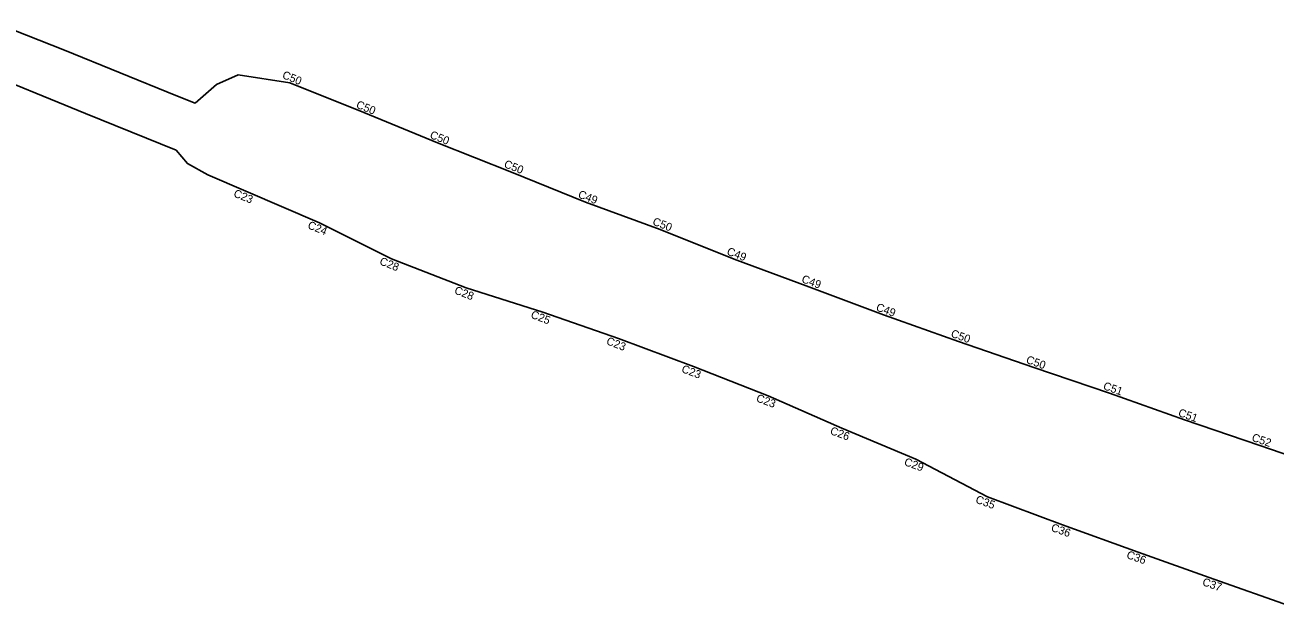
# Model space of a CAD drawing. Extents: x 2164037 to 2171931, y 206073 to 210167.
# Drawn here: x 2165609 to 2166391, y 209174 to 209537 of the extents above; entities that cross this region are included whole.
import ezdxf

# ---------------------------------------------------------------- set-up
doc = ezdxf.new("R2010")
doc.units = 0
doc.layers.add('RD_PD_CstnLmt', color=7, linetype='Continuous')
doc.layers.add('RD_PD_TX_CstnLmt', color=7, linetype='Continuous')

msp = doc.modelspace()

# ---------------------------------------------------------------- linework, layer by layer
at = {"layer": 'RD_PD_CstnLmt'}
for p, q in [((2165774.87, 209500.63), (2165821.08, 209482.09)), ((2165821.08, 209482.09), (2165867.16, 209463.21)), ((2165867.16, 209463.21), (2165913.5, 209445)), ((2165913.5, 209445), (2165959.61, 209426.17)), ((2165747.33, 209433.01), (2165793.39, 209413.29)), ((2165959.61, 209426.17), (2166006.39, 209409.1)), ((2165793.39, 209413.29), (2165838.35, 209390.77)), ((2166006.39, 209409.1), (2166052.59, 209390.51)), ((2165838.35, 209390.77), (2165885.08, 209372.63)), ((2166052.59, 209390.51), (2166099.32, 209373.31)), ((2165885.08, 209372.63), (2165932.94, 209357.45)), ((2166099.32, 209373.31), (2166145.9, 209355.68)), ((2165932.94, 209357.45), (2165980.25, 209340.89)), ((2166145.9, 209355.68), (2166192.88, 209339.17)), ((2165980.25, 209340.89), (2166027.23, 209323.49)), ((2166192.88, 209339.17), (2166239.93, 209322.87)), ((2166027.23, 209323.49), (2166073.89, 209305.26)), ((2166239.93, 209322.87), (2166287.07, 209306.84)), ((2166073.89, 209305.26), (2166119.8, 209284.97)), ((2166287.07, 209306.84), (2166333.96, 209290.11)), ((2166333.96, 209290.11), (2166381.15, 209274.21)), ((2166119.8, 209284.97), (2166166.08, 209265.59)), ((2166381.15, 209274.21), (2166428.15, 209257.81)), ((2166166.08, 209265.59), (2166210.87, 209242.03)), ((2166210.87, 209242.03), (2166257.87, 209224.55)), ((2166257.87, 209224.55), (2166305.07, 209207.58)), ((2166305.07, 209207.58), (2166352.3, 209190.7)), ((2166352.3, 209190.7), (2166399.55, 209173.89))]:
    msp.add_line(p, q, dxfattribs=at)
for points in [[(2165715.77, 209488.06), (2165703.73, 209492.82), (2165634.04, 209521.03), (2165594.5, 209536.83)], [(2165576.85, 209510.24), (2165647.21, 209481.6), (2165703.77, 209458.61)], [(2165715.77, 209488.06), (2165729.07, 209499.69), (2165742.68, 209505.76), (2165774.87, 209500.63)], [(2165703.77, 209458.61), (2165710.83, 209450.29), (2165723.63, 209443.19), (2165747.33, 209433.01)]]:
    msp.add_lwpolyline(points, dxfattribs=at)

# ---------------------------------------------------------------- texts
at = {"layer": 'RD_PD_TX_CstnLmt'}
for s, rotation, p in [('C50', 337.83882, (2165769.69, 209503.82)), ('C50', 338.07756, (2165815.89, 209485.26)), ('C50', 338.31629, (2165861.95, 209466.36)), ('C50', 338.55502, (2165908.28, 209448.13)), ('C23', 337.83882, (2165739.25, 209429.82)), ('C49', 338.79375, (2165954.59, 209429.19)), ('C50', 339.03249, (2166001.14, 209412.18)), ('C24', 338.07756, (2165785.59, 209409.97)), ('C28', 338.31629, (2165830.5, 209387.43)), ('C49', 339.27122, (2166047.55, 209393.49)), ('C49', 339.50995, (2166094.27, 209376.26)), ('C28', 338.55502, (2165877.24, 209369.26)), ('C49', 339.74868, (2166140.83, 209358.62)), ('C25', 338.79375, (2165925.03, 209354.09)), ('C50', 339.98742, (2166187.58, 209342.17)), ('C23', 339.03249, (2165972.24, 209337.54)), ('C50', 340.22615, (2166234.62, 209325.84)), ('C23', 339.27122, (2166019.23, 209320.1)), ('C51', 340.46488, (2166282.78, 209309.42)), ('C23', 339.50995, (2166065.91, 209301.83)), ('C51', 340.70361, (2166329.67, 209292.67)), ('C26', 339.74868, (2166112.09, 209281.42)), ('C52', 340.94235, (2166375.65, 209277.17)), ('C29', 339.98742, (2166158.38, 209262.01)), ('C35', 340.22615, (2166203, 209238.49)), ('C36', 340.46488, (2166250.17, 209220.91)), ('C36', 340.70361, (2166297.38, 209203.91)), ('C37', 340.94235, (2166344.74, 209186.97))]:
    msp.add_text(s, height=5, rotation=rotation, dxfattribs=at).set_placement(p)

doc.saveas('drawing.dxf')
